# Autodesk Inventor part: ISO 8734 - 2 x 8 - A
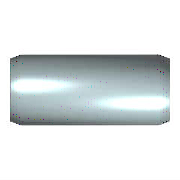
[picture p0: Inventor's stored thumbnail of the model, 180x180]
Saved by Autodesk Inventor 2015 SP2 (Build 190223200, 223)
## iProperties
IsCustomPart: 0
Created: 2012-02
Part Number: ISO 8734 - 2 x 8 - A
Material: Steel
Description: Parallel Pin
Document SubType Name: Modeling
Standard: ISO 8734
Designer: rYan
Standards Organization: DIN
Language: en-US
Size Designation: 2 x 8 - A
Categories: <MemberInstance><Categories><Category DisplayName="Fasteners" InternalName="e4da775c-781d-43d5-af7c-5136215cf5a6" Mnemonic="FSTN"><Category DisplayName="Pins" I
Density: 7.85 g/cm^3
Appearance: Platte
Author: rYan
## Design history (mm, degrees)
sketch "Sketch"
  geometry: C1 r 1 at (0, 0); 1 further point
  constraints: 1 centre point, 1 coincident
  dimensions: "d1" = 2 diameter of C1 (= NND)
extrude "Body" new body sketch "Sketch" distance "d2" = 8 (= NLG); taper "d3" = 0 deg
chamfer "Chamfer1" distance "d4" = 0.35 (= PHH); stored, may be unused: angle "d5" = 15 deg (= FAWI), second distance "d11" = 0.35 (= PHH)
chamfer "Chamfer2" distance "d8" = 0.35 (= PHH); stored, may be unused: angle "d9" = 15 deg (= FAWI), second distance "d12" = 0.35 (= PHH)
body "Solid1"
other parameters: "NND" = 2 [user parameter; used in 1 equation term], "NLG" = 8 [user parameter; used in 1 equation term], "PHH" = 0.35 [user parameter; used in 5 equation terms], "FAWI" = 15 deg [user parameter; used in 2 equation terms], "d13" = 0, "d15" = 0, "d16" = 0, "PHH2" = 0.35 (= PHH) [user parameter], "FAWI2" = 15 deg [user parameter]
